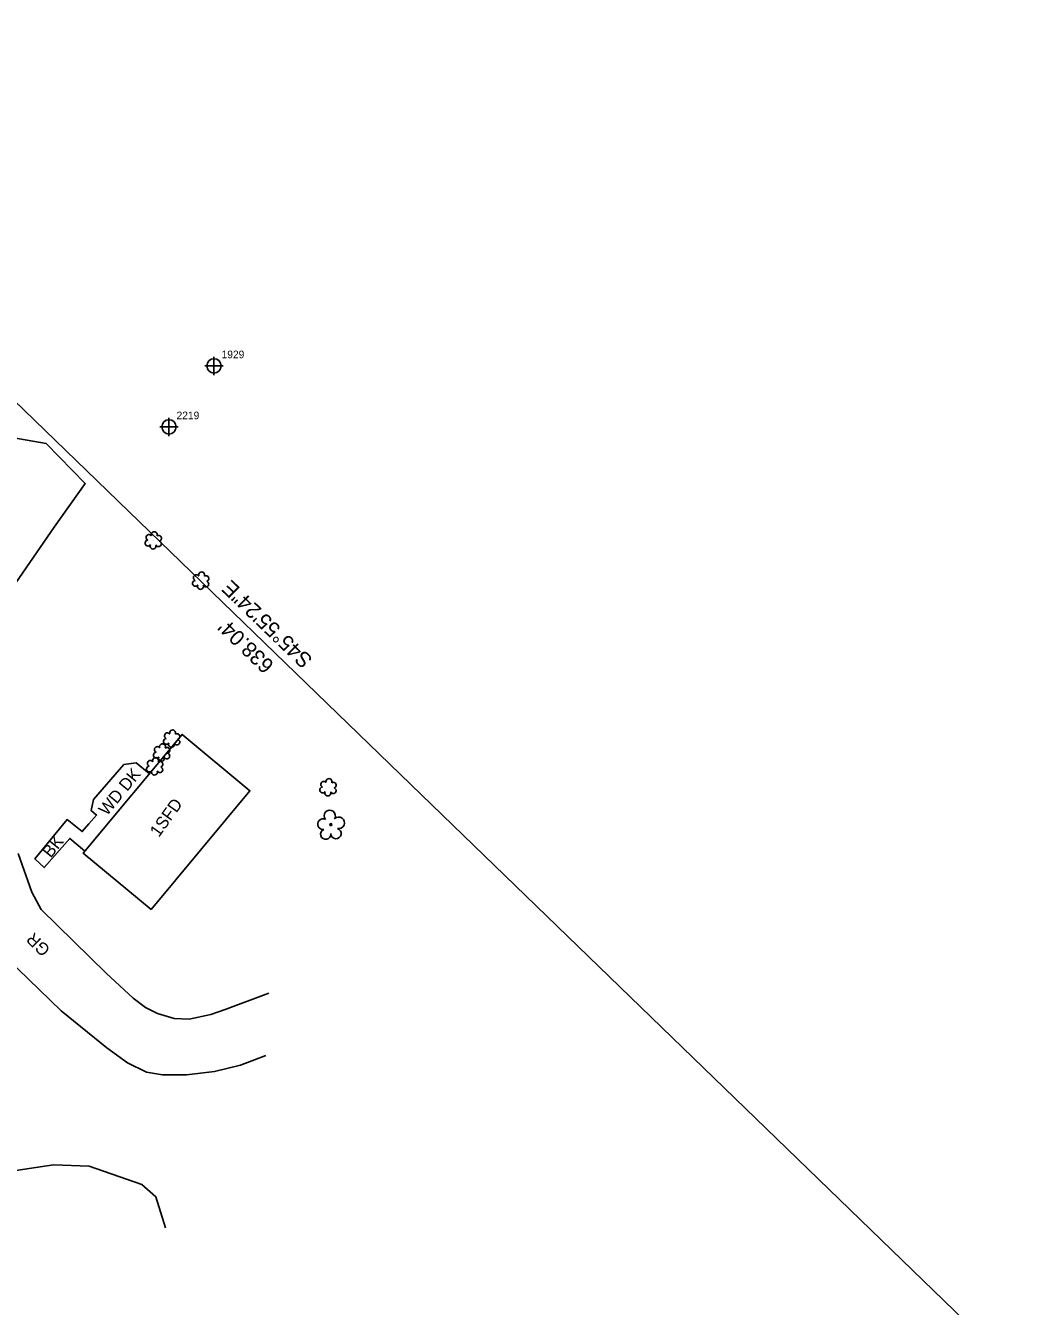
# Model space of a CAD drawing. Extents: x 1653123 to 1656194, y 596584 to 600233.
# Drawn here: x 1654555.6 to 1654883.4, y 598583.3 to 599002.6 of the extents above; entities that cross this region are included whole.
import ezdxf

# ---------------------------------------------------------------- set-up
doc = ezdxf.new("R2010")
doc.units = 0
for name, color, linetype in [('Default Symbol CELL', 7, 'Continuous'), ('Default Symbol Cogo Number', 7, 'Continuous'), ('Exist Building Text', 7, 'Continuous'), ('Exist Other Culture Area Outline Text', 7, 'Continuous'), ('Exist Property Line', 7, 'Continuous'), ('Exist Property Line Text', 7, 'Continuous'), ('Exist Roads Soil Text', 7, 'Continuous'), ('Exist Vegetation Tree CELL', 7, 'Continuous'), ('Exist Vegetation Woods Line', 7, 'Continuous'), ('Prop Easement Construction', 7, 'Continuous'), ('Prop Easement Permanent Drainage Station Offsets', 7, 'Continuous'), ('Prop ROW Station Offsets', 7, 'Continuous'), ('Prop Superelevation Label', 7, 'Continuous')]:
    doc.layers.add(name, color=color, linetype=linetype)

# ---------------------------------------------------------------- blocks, each defined once
blk = doc.blocks.new('DEFAULT SYMBOL')
at = {"layer": 'Default Symbol CELL'}
for points in [[(-0.06, 0), (0, 0)], [(0, 0.06), (0, 0)], [(0, 0), (0.06, 0)], [(0, 0), (0, -0.06)]]:
    blk.add_lwpolyline(points, dxfattribs=at)
blk.add_circle((0, 0), 0.0469, dxfattribs=at)

msp = doc.modelspace()

# ---------------------------------------------------------------- linework, layer by layer
at = {"layer": 'Exist Property Line'}
msp.add_lwpolyline([(1654424.99, 599002.56), (1654883.37, 598558.72)], dxfattribs=at)
at = {"layer": 'Exist Vegetation Tree CELL'}
msp.add_line((1654655.48, 598741.02), (1654655.48, 598741.02), dxfattribs=at)
msp.add_circle((1654655.48, 598741.02), 0.326, dxfattribs=at)
for centre, radius, start, end in [((1654655.09, 598743.89), 1.86, 330.1651, 219.7134), ((1654658.03, 598741.61), 1.9, 257.1011, 134.1999), ((1654652.87, 598741.17), 1.73, 62.6636, 279.3457), ((1654653.77, 598737.9), 1.69, 111.5671, 6.231), ((1654657.15, 598738.12), 1.7, 181.2822, 74.56)]:
    msp.add_arc(centre, radius, start, end, dxfattribs=at)
at = {"layer": 'Exist Vegetation Woods Line'}
msp.add_lwpolyline([(1654545.03, 598626.69), (1654564.73, 598629.62), (1654576.43, 598629.27), (1654593.6, 598623.22), (1654598.21, 598619.2), (1654601.32, 598609.07)], dxfattribs=at)
at = {"layer": 'Prop Easement Construction'}
for points in [[(1654552.41, 598820.2), (1654564.89, 598838.34), (1654575.1, 598852.65), (1654562.36, 598865.76), (1654546.59, 598868.52)], [(1654635.14, 598685.84), (1654620.9, 598680.51), (1654616.23, 598678.91), (1654609.13, 598677.4), (1654604.16, 598677.59), (1654598.72, 598679.19), (1654594.8, 598681.21), (1654590.72, 598684.21), (1654581.98, 598692.45), (1654560.68, 598713.27), (1654557.57, 598718.88), (1654553.11, 598731.53)], [(1654545.87, 598700.72), (1654567.26, 598680.09), (1654582.16, 598667.93), (1654588.87, 598663.06), (1654595.1, 598660.03), (1654600.38, 598659.09), (1654608.27, 598659.13), (1654617.38, 598660.25), (1654625.94, 598662.31), (1654634.21, 598665.43)]]:
    msp.add_lwpolyline(points, dxfattribs=at)
at = {"layer": 'Prop Easement Permanent Drainage Station Offsets'}
msp.add_lwpolyline([(1654596.66, 598713.22), (1654628.98, 598752.12), (1654606.77, 598770.57), (1654574.46, 598731.67)], close=True, dxfattribs=at)
at = {"layer": 'Prop ROW Station Offsets'}
msp.add_lwpolyline([(1654595.97, 598757.78), (1654591.8, 598761.27), (1654587.77, 598760.71), (1654577.78, 598749.3), (1654577.06, 598745.62), (1654578.79, 598744.13), (1654576.25, 598741.32), (1654574.11, 598738.75), (1654569.15, 598742.68), (1654558.62, 598729.79), (1654561.68, 598726.99), (1654570, 598736.51), (1654574.81, 598732.5)], dxfattribs=at)
at = {"layer": 'Prop Superelevation Label'}
for p, q in [((1654597.43, 598833.88), (1654597.43, 598833.88)), ((1654612.94, 598820.71), (1654612.94, 598820.71)), ((1654603.46, 598768.97), (1654603.46, 598768.97)), ((1654600.15, 598764.45), (1654600.15, 598764.45)), ((1654597.88, 598759.92), (1654597.88, 598759.92)), ((1654654.62, 598753.07), (1654654.62, 598753.07))]:
    msp.add_line(p, q, dxfattribs=at)
for centre, radius, start, end in [((1654595.95, 598835.01), 0.968, 35.8908, 245.4216), ((1654597.66, 598835.92), 0.99, 334.8391, 200.4717), ((1654599.1, 598834.75), 0.929, 284.4567, 126.0861), ((1654595.63, 598833.18), 0.955, 95.1099, 327.9534), ((1654597.3, 598832.2), 0.984, 151.2797, 21.387), ((1654599.07, 598832.95), 0.937, 204.9913, 73.4601), ((1654611.46, 598821.83), 0.968, 35.8908, 245.4216), ((1654613.17, 598822.75), 0.99, 334.8391, 200.4717), ((1654611.14, 598820), 0.955, 95.1099, 327.9534), ((1654612.82, 598819.02), 0.984, 151.2797, 21.387), ((1654614.58, 598819.78), 0.937, 204.9913, 73.4601), ((1654614.62, 598821.57), 0.929, 284.4567, 126.0861), ((1654601.66, 598768.27), 0.955, 95.1099, 327.9534), ((1654601.98, 598770.1), 0.968, 35.8908, 245.4216), ((1654603.69, 598771.01), 0.99, 334.8391, 200.4717), ((1654605.1, 598768.04), 0.937, 204.9913, 73.4601), ((1654605.13, 598769.84), 0.929, 284.4567, 126.0861), ((1654598.35, 598763.74), 0.955, 95.1099, 327.9534), ((1654598.67, 598765.58), 0.968, 35.8908, 245.4216), ((1654600.38, 598766.49), 0.99, 334.8391, 200.4717), ((1654601.79, 598763.52), 0.937, 204.9913, 73.4601), ((1654601.83, 598765.32), 0.929, 284.4567, 126.0861), ((1654603.33, 598767.29), 0.984, 151.2797, 21.387), ((1654596.08, 598759.21), 0.955, 95.1099, 327.9534), ((1654596.4, 598761.05), 0.968, 35.8908, 245.4216), ((1654598.11, 598761.96), 0.99, 334.8391, 200.4717), ((1654599.52, 598758.99), 0.937, 204.9913, 73.4601), ((1654599.55, 598760.79), 0.929, 284.4567, 126.0861), ((1654600.03, 598762.76), 0.984, 151.2797, 21.387), ((1654597.75, 598758.24), 0.984, 151.2797, 21.387), ((1654654.85, 598755.11), 0.99, 334.8391, 200.4717), ((1654652.82, 598752.37), 0.955, 95.1099, 327.9534), ((1654653.14, 598754.2), 0.968, 35.8908, 245.4216), ((1654654.49, 598751.39), 0.984, 151.2797, 21.387), ((1654656.26, 598752.14), 0.937, 204.9913, 73.4601), ((1654656.29, 598753.94), 0.929, 284.4567, 126.0861)]:
    msp.add_arc(centre, radius, start, end, dxfattribs=at)

# ---------------------------------------------------------------- block references
at = {"layer": 'Default Symbol CELL', "xscale": 50, "yscale": 50}
for p in [(1654617.21, 598891.18), (1654602.48, 598871.22)]:
    msp.add_blockref('DEFAULT SYMBOL', p, dxfattribs=at)

# ---------------------------------------------------------------- texts
at = {"layer": 'Default Symbol Cogo Number'}
for s, p in [('1929', (1654619.71, 598893.68)), ('2219', (1654604.98, 598873.72))]:
    msp.add_text(s, height=2.5, dxfattribs=at).set_placement(p)
at = {"layer": 'Exist Building Text'}
msp.add_text('1SFD', height=4, rotation=54.3896, dxfattribs=at).set_placement((1654599.18, 598736.67))
at = {"layer": 'Exist Other Culture Area Outline Text'}
for s, rotation, p in [('WD DK', 50.5288, (1654582.19, 598743.67)), ('BK', 51.2405, (1654563.81, 598729.89))]:
    msp.add_text(s, height=4, rotation=rotation, dxfattribs=at).set_placement(p)
at = {"layer": 'Exist Property Line Text'}
for s, p in [('S45%%d55\'24"E', (1654649.81, 598795.31)), ("638.04'", (1654637.18, 598793.62))]:
    msp.add_text(s, height=5, rotation=135.9232, dxfattribs=at).set_placement(p)
at = {"layer": 'Exist Roads Soil Text'}
msp.add_text('GR', height=4, rotation=135.6474, dxfattribs=at).set_placement((1654563.94, 598700.37))

doc.saveas('drawing.dxf')
